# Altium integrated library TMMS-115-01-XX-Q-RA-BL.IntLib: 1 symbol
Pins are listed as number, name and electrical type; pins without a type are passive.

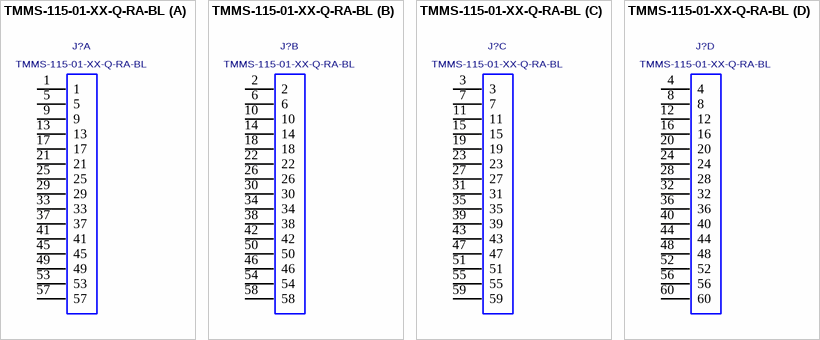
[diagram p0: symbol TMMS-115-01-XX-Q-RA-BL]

## TMMS-115-01-XX-Q-RA-BL
designator J?
2MM QUAD ROW FULL SHROUD TERMINAL ASM.; MANUFACTURER: SAMTEC
footprint TMMS-115-01-XX-Q-RA-BL
part A pins: 1, 5, 9, 13, 17, 21, 25, 29, 33, 37, 41, 45, 49, 53, 57
part B pins: 2, 6, 10, 14, 18, 22, 26, 30, 34, 38, 42, 46, 50, 54, 58
part C pins: 3, 7, 11, 15, 19, 23, 27, 31, 35, 39, 43, 47, 51, 55, 59
part D pins: 4, 8, 12, 16, 20, 24, 28, 32, 36, 40, 44, 48, 52, 56, 60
